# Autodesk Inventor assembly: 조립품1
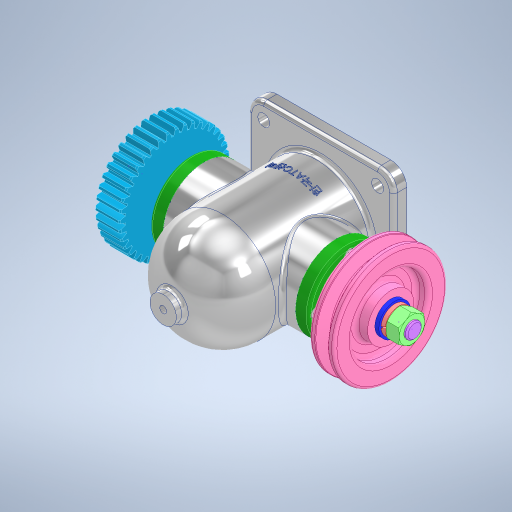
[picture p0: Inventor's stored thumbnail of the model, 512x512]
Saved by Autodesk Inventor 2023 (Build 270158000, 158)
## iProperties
Created: 2025-04
Part Number: 조립품1
Document SubType Name: Assembly
Designer: Admin
Author: Admin
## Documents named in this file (14)
- C:\Users\Admin\Desktop\750406V1003\조립품1.iam
- C:\Users\Admin\Desktop\750406V1003\부품1.ipt
- C:\Users\Admin\Desktop\750406V1003\750406V1003\깊은 홈 볼 베어링 6203.ipt
- C:\Users\Admin\Desktop\750406V1003\750406V1003\축.ipt
- C:\Users\Admin\Desktop\750406V1003\750406V1003\커버.ipt
- C:\Users\Admin\Desktop\750406V1003\750406V1003\오일 실 26 38 8.ipt
- C:\Users\Admin\Desktop\750406V1003\750406V1003\6각 구멍붙이 볼트 M4x12.ipt
- C:\Users\Admin\Desktop\750406V1003\750406V1003\칼라.ipt
- C:\Users\Admin\Desktop\750406V1003\750406V1003\평행 키 5x5x12.ipt
- C:\Users\Admin\Desktop\750406V1003\750406V1003\스퍼기어.ipt
- C:\Users\Admin\Desktop\750406V1003\750406V1003\V 벨트 풀리.ipt
- C:\Users\Admin\Desktop\750406V1003\750406V1003\평와셔 M12.ipt
- C:\Users\Admin\Desktop\750406V1003\750406V1003\스프링 와셔 M12.ipt
- C:\Users\Admin\Desktop\750406V1003\750406V1003\6각 너트 M12x1.ipt
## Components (11 placed, 3 different names)
1. 6각 구멍붙이 볼트 M4x12:1
2. 6각 구멍붙이 볼트 M4x12:2
3. 6각 구멍붙이 볼트 M4x12:3
4. 6각 구멍붙이 볼트 M4x12:4
5. 6각 구멍붙이 볼트 M4x12:5
6. 6각 구멍붙이 볼트 M4x12:6
7. 6각 구멍붙이 볼트 M4x12:7
8. 6각 구멍붙이 볼트 M4x12:8
9. V 벨트 풀리:1
10. 6각 너트 M12x1:2
11. 6각 너트 M12x1:3
